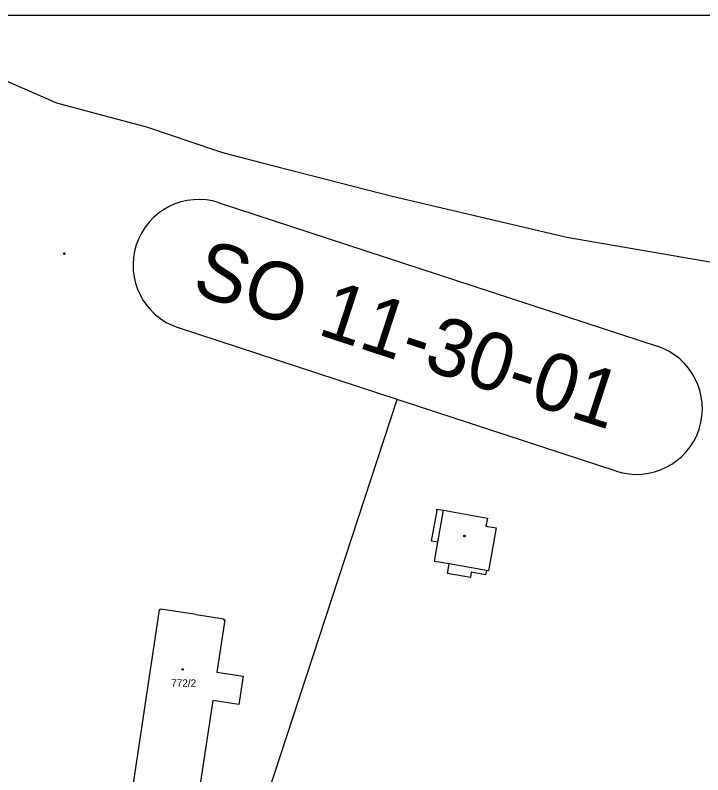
# Model space of a CAD drawing. Extents: x -728802 to -728097, y -1073200 to -1072700.
# Drawn here: x -728500.3 to -728343.6, y -1072873.2 to -1072700 of the extents above; entities that cross this region are included whole.
import ezdxf

# ---------------------------------------------------------------- set-up
doc = ezdxf.new("R2010")
doc.units = 0
for name, color, linetype in [('Hranice parcel', 7, 'Continuous'), ('K_31_listy_JŽM', 7, 'Continuous'), ('ZZZ_popisky', 7, 'Continuous')]:
    doc.layers.add(name, color=color, linetype=linetype)

msp = doc.modelspace()

# ---------------------------------------------------------------- linework, layer by layer
at = {"layer": 'Hranice parcel'}
for p, q in [((-728405.41, -1072819.96), (-728404.1, -1072812.94)), ((-728404.22, -1072812.92), (-728404.16, -1072812.64)), ((-728404.1, -1072812.94), (-728404.22, -1072812.92)), ((-728404.16, -1072812.64), (-728402.67, -1072812.92)), ((-728403.95, -1072820.22), (-728402.67, -1072812.92)), ((-728402.67, -1072812.92), (-728392.67, -1072814.72)), ((-728392.67, -1072814.72), (-728392.99, -1072816.55)), ((-728392.99, -1072816.55), (-728390.7, -1072816.95)), ((-728390.7, -1072816.95), (-728392.43, -1072826.74)), ((-728403.95, -1072820.22), (-728405.41, -1072819.96)), ((-728404.72, -1072824.57), (-728403.95, -1072820.22)), ((-728401.38, -1072825.16), (-728404.72, -1072824.57)), ((-728401.76, -1072827.33), (-728401.38, -1072825.16)), ((-728392.9, -1072826.65), (-728401.38, -1072825.16)), ((-728396.54, -1072828.25), (-728401.76, -1072827.33)), ((-728396.33, -1072827.06), (-728396.54, -1072828.25)), ((-728393.07, -1072827.64), (-728396.33, -1072827.06)), ((-728392.9, -1072826.65), (-728393.07, -1072827.64)), ((-728392.43, -1072826.74), (-728392.9, -1072826.65)), ((-728459.04, -1072836.7), (-728452.76, -1072837.65)), ((-728452.51, -1072837.92), (-728454.31, -1072849.83)), ((-728452.76, -1072837.65), (-728452.8, -1072837.87)), ((-728452.8, -1072837.87), (-728452.51, -1072837.92)), ((-728454.31, -1072849.83), (-728448.33, -1072850.73)), ((-728448.33, -1072850.73), (-728449.29, -1072857.19)), ((-728455.28, -1072856.27), (-728460.15, -1072888.97)), ((-728449.29, -1072857.19), (-728455.28, -1072856.27))]:
    msp.add_line(p, q, dxfattribs=at)
for points in [[(-728560.99, -1072700), (-728556.68, -1072703.94), (-728549.87, -1072701.63), (-728519.4, -1072710.73), (-728519.03, -1072709.42), (-728508.64, -1072712.27), (-728490.92, -1072719.99), (-728470.17, -1072725.55), (-728454.65, -1072730.81), (-728452.72, -1072731.42), (-728444.29, -1072733.58), (-728414.4, -1072741.24), (-728374.54, -1072750.66), (-728337.07, -1072757.11)], [(-728459.04, -1072836.7), (-728467.13, -1072835.48), (-728467.16, -1072835.65), (-728467.45, -1072835.63), (-728475.14, -1072886.87)]]:
    msp.add_lwpolyline(points, dxfattribs=at)
for centre in [(-728489.09, -1072754.4), (-728397.88, -1072818.79), (-728462.1, -1072849.22)]:
    msp.add_circle(centre, 0.175, dxfattribs=at)
at = {"layer": 'K_31_listy_JŽM'}
msp.add_lwpolyline([(-728800, -1073200), (-728800, -1072700), (-728100, -1072700), (-728100, -1073200), (-728800, -1073200)], dxfattribs=at)
at = {"layer": 'ZZZ_popisky'}
for points in [[(-728453.77, -1072742.78), (-728353.99, -1072775.47)], [(-728496.07, -1073040.51), (-728413.22, -1072787.63), (-728463.11, -1072771.29)], [(-728363.33, -1072803.98), (-728413.22, -1072787.63)]]:
    msp.add_lwpolyline(points, dxfattribs=at)
for centre, start, end in [((-728458.44, -1072757.03), 71.8591, 251.8591), ((-728358.66, -1072789.73), 251.8591, 71.8591)]:
    msp.add_arc(centre, 15, start, end, dxfattribs=at)

# ---------------------------------------------------------------- texts
at = {"layer": 'Hranice parcel'}
msp.add_text('772/2', height=1.7, dxfattribs=at).set_placement((-728464.73, -1072853.17))
at = {"layer": 'ZZZ_popisky'}
msp.add_text('SO 11-30-01', height=13.125, rotation=341.8591, dxfattribs=at).set_placement((-728460.46, -1072763.28))

doc.saveas('drawing.dxf')
